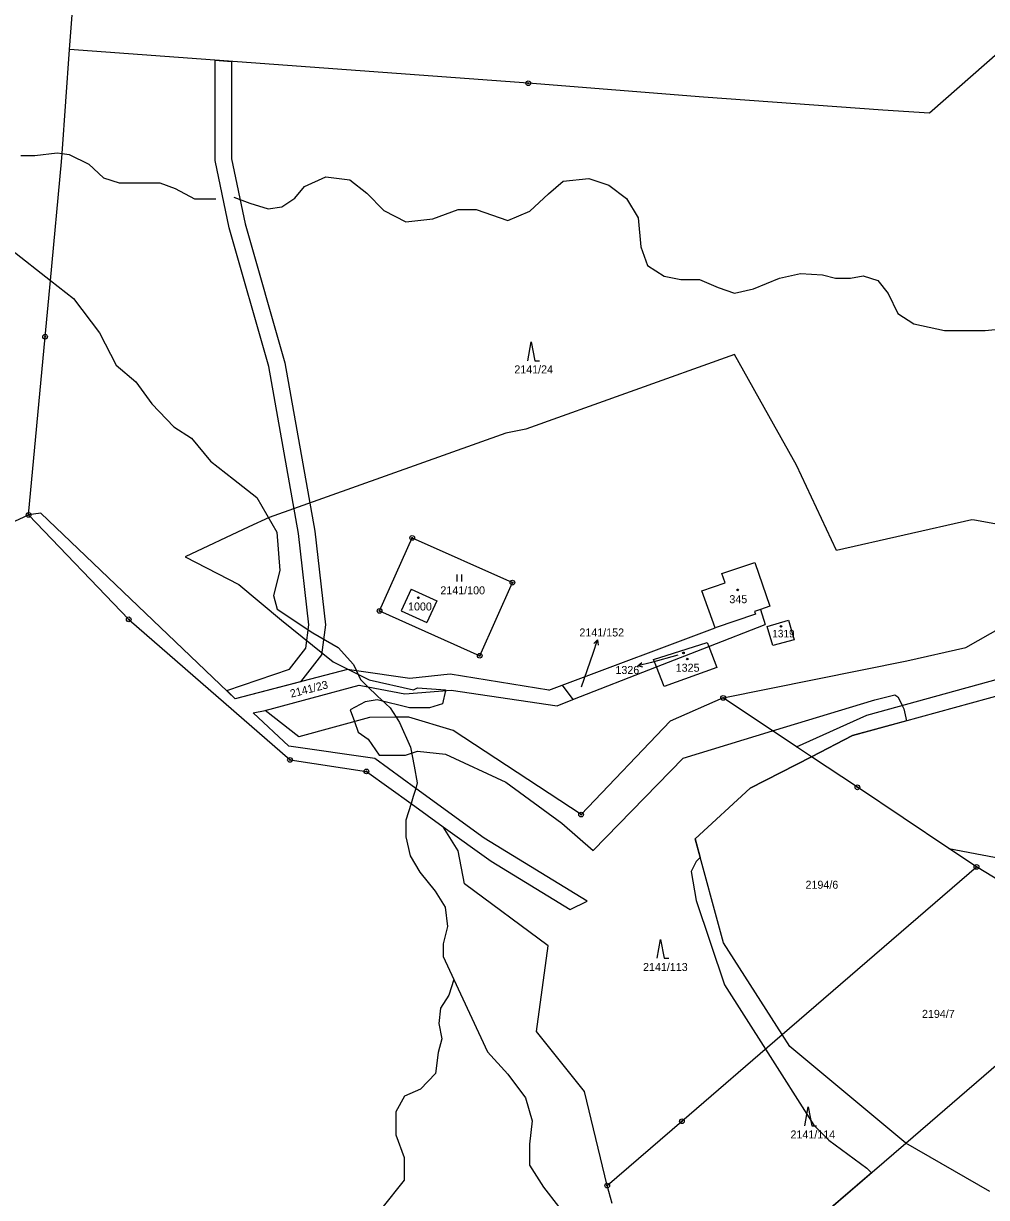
# Model space of a CAD drawing. Extents: x -439246 to -433691, y -1130252 to -1121148.
# Drawn here: x -435202 to -434997.5, y -1125650.6 to -1125401.2 of the extents above; entities that cross this region are included whole.
import ezdxf

# ---------------------------------------------------------------- set-up
doc = ezdxf.new("R2010")
doc.units = 0
for name, color, linetype in [('Vrstva 1', 7, 'Continuous'), ('Vrstva 16', 7, 'Continuous'), ('Vrstva 18', 7, 'Continuous'), ('Vrstva 19', 7, 'Continuous'), ('Vrstva 24', 7, 'Continuous'), ('Vrstva 25', 7, 'Continuous'), ('Vrstva 3', 7, 'Continuous'), ('Vrstva 30', 7, 'Continuous'), ('Vrstva 37', 7, 'Continuous'), ('Vrstva 4', 7, 'Continuous'), ('Vrstva 52', 7, 'Continuous')]:
    doc.layers.add(name, color=color, linetype=linetype)

msp = doc.modelspace()

# ---------------------------------------------------------------- linework, layer by layer
at = {"layer": 'Vrstva 1'}
for p, q in [((-435192.2, -1125406.77), (-435191.19, -1125392.8)), ((-435193.8, -1125428.86), (-435192.2, -1125406.77)), ((-435094.79, -1125413.92), (-435192.2, -1125406.77)), ((-435197.39, -1125467.76), (-435196.28, -1125455.81)), ((-435200.92, -1125505.62), (-435197.39, -1125467.76))]:
    msp.add_line(p, q, dxfattribs=at)
for points in [[(-434988.68, -1125401.95), (-435009.59, -1125420.25)], [(-435057.61, -1125416.9), (-435094.79, -1125413.92)], [(-435019.5, -1125419.63), (-435057.61, -1125416.9)], [(-435009.59, -1125420.25), (-435019.5, -1125419.63)], [(-435193.93, -1125430.63), (-435193.8, -1125428.86)], [(-435196.28, -1125455.81), (-435193.93, -1125430.63)], [(-435234.91, -1125521.29), (-435200.92, -1125505.62)], [(-435198.33, -1125505.22), (-435200.92, -1125505.62)], [(-435200.92, -1125505.62), (-435179.64, -1125527.79)], [(-435157.01, -1125544.65), (-435198.33, -1125505.22)], [(-435126.37, -1125526.01), (-435119.43, -1125510.49)], [(-435119.43, -1125510.49), (-435098.16, -1125520)], [(-435057.91, -1125521.71), (-435052.99, -1125520.03), (-435053.65, -1125518.08), (-435046.69, -1125515.7)], [(-435046.69, -1125515.7), (-435043.49, -1125524.97), (-435045.5, -1125525.68)], [(-435119.69, -1125521.36), (-435121.77, -1125525.97)], [(-435119.69, -1125521.36), (-435114.22, -1125523.83)], [(-435105.1, -1125535.52), (-435098.16, -1125520)], [(-435001.84, -1125533.79), (-434976.15, -1125519.18)], [(-435114.22, -1125523.83), (-435116.3, -1125528.43)], [(-435055.1, -1125529.6), (-435057.91, -1125521.71)], [(-435126.37, -1125526.01), (-435105.1, -1125535.52)], [(-435121.77, -1125525.97), (-435116.3, -1125528.43)], [(-435045.5, -1125525.68), (-435046.74, -1125526.12)], [(-435046.74, -1125526.12), (-435046.56, -1125526.71)], [(-435045.5, -1125525.68), (-435044.49, -1125528.87)], [(-435179.64, -1125527.79), (-435145.39, -1125557.65)], [(-435056.45, -1125533.55), (-435044.49, -1125528.87)], [(-435046.56, -1125526.71), (-435055.1, -1125529.6)], [(-435044.06, -1125529.34), (-435039.49, -1125527.98), (-435038.32, -1125532.12), (-435042.87, -1125533.32), (-435044.06, -1125529.34)], [(-435087.62, -1125541.8), (-435055.1, -1125529.6)], [(-435068.18, -1125536.32), (-435056.78, -1125532.69), (-435056.45, -1125533.55)], [(-435067.57, -1125537.9), (-435056.45, -1125533.55)], [(-435056.45, -1125533.55), (-435054.73, -1125538.01), (-435065.96, -1125542.06), (-435067.57, -1125537.9)], [(-435014.37, -1125536.57), (-435001.84, -1125533.79)], [(-435067.57, -1125537.9), (-435068.18, -1125536.32)], [(-435133.16, -1125538.45), (-435157.01, -1125544.65)], [(-435131.3, -1125538.72), (-435133.16, -1125538.45)], [(-435119.97, -1125540.36), (-435131.3, -1125538.72)], [(-435085.3, -1125544.84), (-435067.57, -1125537.9)], [(-435053.4, -1125544.49), (-435014.37, -1125536.57)], [(-435022.88, -1125548.13), (-434980.29, -1125536.37)], [(-435111.41, -1125539.45), (-435119.97, -1125540.36)], [(-435090.44, -1125542.86), (-435111.41, -1125539.45)], [(-435150.69, -1125547.12), (-435130.69, -1125541.75)], [(-435130.69, -1125541.75), (-435128.84, -1125542.11)], [(-435128.84, -1125542.11), (-435120.99, -1125543.62)], [(-435120.99, -1125543.62), (-435111.15, -1125542.81)], [(-435111.15, -1125542.81), (-435088.64, -1125546.15)], [(-435090.44, -1125542.86), (-435087.62, -1125541.8)], [(-435087.62, -1125541.8), (-435085.3, -1125544.84)], [(-435025.91, -1125552.49), (-434986.23, -1125541.55)], [(-435088.64, -1125546.15), (-435085.3, -1125544.84)], [(-435053.4, -1125544.49), (-435064.66, -1125549.42)], [(-435037.86, -1125554.84), (-435053.4, -1125544.49)], [(-435153.19, -1125547.67), (-435150.69, -1125547.12)], [(-435145.67, -1125554.75), (-435153.19, -1125547.67)], [(-435143.52, -1125552.73), (-435150.69, -1125547.12)], [(-435128.52, -1125548.63), (-435143.52, -1125552.73)], [(-435122.85, -1125548.59), (-435128.52, -1125548.63)], [(-435120.15, -1125548.57), (-435122.85, -1125548.59)], [(-435110.75, -1125551.4), (-435120.15, -1125548.57)], [(-435037.86, -1125554.84), (-435022.88, -1125548.13)], [(-435064.66, -1125549.42), (-435083.57, -1125569.26)], [(-435083.57, -1125569.26), (-435110.75, -1125551.4)], [(-435034.64, -1125556.98), (-435025.91, -1125552.49)], [(-435127.38, -1125557.37), (-435145.67, -1125554.75)], [(-435034.64, -1125556.98), (-435037.86, -1125554.84)], [(-435145.39, -1125557.65), (-435129.16, -1125560.08)], [(-435118.69, -1125563.7), (-435127.38, -1125557.37)], [(-435047.65, -1125563.68), (-435034.64, -1125556.98)], [(-435024.89, -1125563.47), (-435034.64, -1125556.98)], [(-435129.16, -1125560.08), (-435119.68, -1125566.92)], [(-435104.14, -1125574.29), (-435118.69, -1125563.7)], [(-435059.34, -1125574.38), (-435047.65, -1125563.68)], [(-435005.44, -1125576.46), (-435024.89, -1125563.47)], [(-435119.68, -1125566.92), (-435112.83, -1125571.87)], [(-435109.68, -1125576.97), (-435112.83, -1125571.87)], [(-435112.83, -1125571.87), (-435102.66, -1125579.13)], [(-435082.3, -1125587.67), (-435104.14, -1125574.29)], [(-435053.34, -1125596.52), (-435059.34, -1125574.38)], [(-435108.32, -1125583.95), (-435109.68, -1125576.97)], [(-435005.44, -1125576.46), (-434937.66, -1125589.35)], [(-434999.6, -1125580.36), (-435005.44, -1125576.46)], [(-435102.66, -1125579.13), (-435085.88, -1125589.41)], [(-435040.84, -1125616), (-434999.6, -1125580.36)], [(-434968.52, -1125599.25), (-434999.6, -1125580.36)], [(-435090.58, -1125597.13), (-435108.32, -1125583.95)], [(-435085.88, -1125589.41), (-435082.3, -1125587.67)], [(-435093.02, -1125615.36), (-435090.58, -1125597.13)], [(-435040.84, -1125616), (-435053.34, -1125596.52)], [(-435014.64, -1125639.05), (-434968.52, -1125599.25)], [(-435082.87, -1125628.06), (-435093.02, -1125615.36)], [(-435062.15, -1125634.4), (-435040.84, -1125616)], [(-435039.22, -1125618.53), (-435040.84, -1125616)], [(-435014.64, -1125639.05), (-435039.22, -1125618.53)], [(-435078.02, -1125648.06), (-435082.87, -1125628.06)], [(-435078.02, -1125648.06), (-435062.15, -1125634.4)], [(-435038.13, -1125659.3), (-435014.64, -1125639.05)], [(-434996.75, -1125649.32), (-435014.64, -1125639.05)], [(-435076.96, -1125651.87), (-435078.02, -1125648.06)]]:
    msp.add_lwpolyline(points, dxfattribs=at)
at = {"layer": 'Vrstva 16'}
for p, q in [((-435081.03, -1125534.99), (-435080.07, -1125532.15)), ((-435068.64, -1125536.93), (-435071.54, -1125537.7))]:
    msp.add_line(p, q, dxfattribs=at)
for points in [[(-435080.87, -1125532.94), (-435080.07, -1125532.15), (-435079.92, -1125533.25)], [(-435083.45, -1125542.16), (-435081.03, -1125534.99)], [(-435063.01, -1125535.43), (-435068.64, -1125536.93)], [(-435070.44, -1125537.93), (-435071.54, -1125537.7), (-435070.7, -1125536.96)]]:
    msp.add_lwpolyline(points, dxfattribs=at)
at = {"layer": 'Vrstva 24'}
for centre, radius in [((-435094.79, -1125413.92), 0.5), ((-435094.79, -1125413.92), 0.1), ((-435197.39, -1125467.76), 0.5), ((-435197.39, -1125467.76), 0.1), ((-435200.92, -1125505.62), 0.5), ((-435200.92, -1125505.62), 0.1), ((-435119.43, -1125510.49), 0.5), ((-435119.43, -1125510.49), 0.1), ((-435098.16, -1125520), 0.5), ((-435098.16, -1125520), 0.1), ((-435126.37, -1125526.01), 0.5), ((-435126.37, -1125526.01), 0.1), ((-435179.64, -1125527.79), 0.5), ((-435179.64, -1125527.79), 0.1), ((-435105.1, -1125535.52), 0.5), ((-435105.1, -1125535.52), 0.1), ((-435053.4, -1125544.49), 0.5), ((-435053.4, -1125544.49), 0.1), ((-435145.39, -1125557.65), 0.5), ((-435145.39, -1125557.65), 0.1), ((-435129.16, -1125560.08), 0.5), ((-435129.16, -1125560.08), 0.1), ((-435024.89, -1125563.47), 0.5), ((-435024.89, -1125563.47), 0.1), ((-435083.57, -1125569.26), 0.5), ((-435083.57, -1125569.26), 0.1), ((-434999.6, -1125580.36), 0.5), ((-434999.6, -1125580.36), 0.1), ((-435062.15, -1125634.4), 0.5), ((-435062.15, -1125634.4), 0.1), ((-435078.02, -1125648.06), 0.5), ((-435078.02, -1125648.06), 0.1)]:
    msp.add_circle(centre, radius, dxfattribs=at)
at = {"layer": 'Vrstva 25'}
for p, q in [((-435109.89, -1125519.78), (-435109.89, -1125518.28)), ((-435108.89, -1125519.78), (-435108.89, -1125518.28))]:
    msp.add_line(p, q, dxfattribs=at)
for points in [[(-435094.87, -1125472.85), (-435094.17, -1125468.85), (-435093.37, -1125472.85), (-435092.37, -1125472.85)], [(-435067.41, -1125599.79), (-435066.71, -1125595.79), (-435065.91, -1125599.79), (-435064.91, -1125599.79)], [(-435036.08, -1125635.35), (-435035.38, -1125631.35), (-435034.58, -1125635.35), (-435033.58, -1125635.35)]]:
    msp.add_lwpolyline(points, dxfattribs=at)
for centre in [(-435050.31, -1125521.53), (-435118.13, -1125523.21), (-435041.1, -1125529.29), (-435061.83, -1125534.91), (-435061.01, -1125536.22)]:
    msp.add_circle(centre, 0.175, dxfattribs=at)
at = {"layer": 'Vrstva 3'}
for points in [[(-435057.91, -1125521.71), (-435052.99, -1125520.03), (-435053.65, -1125518.08), (-435046.69, -1125515.7)], [(-435046.69, -1125515.7), (-435043.49, -1125524.97), (-435045.5, -1125525.68)], [(-435119.69, -1125521.36), (-435121.77, -1125525.97)], [(-435119.69, -1125521.36), (-435114.22, -1125523.83)], [(-435114.22, -1125523.83), (-435116.3, -1125528.43)], [(-435055.1, -1125529.6), (-435057.91, -1125521.71)], [(-435121.77, -1125525.97), (-435116.3, -1125528.43)], [(-435045.5, -1125525.68), (-435046.74, -1125526.12)], [(-435046.74, -1125526.12), (-435046.56, -1125526.71)], [(-435046.56, -1125526.71), (-435055.1, -1125529.6)], [(-435044.06, -1125529.34), (-435039.49, -1125527.98), (-435038.32, -1125532.12), (-435042.87, -1125533.32), (-435044.06, -1125529.34)], [(-435068.18, -1125536.32), (-435056.78, -1125532.69), (-435056.45, -1125533.55)], [(-435056.45, -1125533.55), (-435054.73, -1125538.01), (-435065.96, -1125542.06), (-435067.57, -1125537.9)], [(-435067.57, -1125537.9), (-435068.18, -1125536.32)]]:
    msp.add_lwpolyline(points, dxfattribs=at)
at = {"layer": 'Vrstva 30'}
msp.add_lwpolyline([(-435161.3, -1125409.04), (-435157.8, -1125409.3), (-435157.78, -1125429.96), (-435154.88, -1125443.79), (-435146.49, -1125473.3), (-435140.11, -1125509.06), (-435137.83, -1125528.98), (-435138.72, -1125535.34), (-435143.16, -1125541.05), (-435157.01, -1125544.65), (-435158.82, -1125542.92), (-435145.53, -1125538.39), (-435142.06, -1125533.93), (-435141.36, -1125528.93), (-435143.58, -1125509.56), (-435149.91, -1125474.08), (-435158.28, -1125444.63), (-435161.28, -1125430.32), (-435161.3, -1125409.04)], dxfattribs=at)
at = {"layer": 'Vrstva 37'}
for centre in [(-435050.31, -1125521.53), (-435118.13, -1125523.21), (-435041.1, -1125529.29), (-435061.01, -1125536.22)]:
    msp.add_circle(centre, 0.175, dxfattribs=at)
at = {"layer": 'Vrstva 4'}
for points in [[(-435199.56, -1125429.27), (-435194.81, -1125428.71)], [(-435194.81, -1125428.71), (-435193.8, -1125428.86)], [(-435193.8, -1125428.86), (-435192.31, -1125429.08)], [(-435192.31, -1125429.08), (-435188.1, -1125431.09)], [(-435202.56, -1125429.27), (-435199.56, -1125429.27)], [(-435188.1, -1125431.09), (-435184.99, -1125433.98)], [(-435184.99, -1125433.98), (-435181.68, -1125435.07)], [(-435142.28, -1125435.84), (-435137.77, -1125433.83)], [(-435137.77, -1125433.83), (-435132.67, -1125434.45)], [(-435181.68, -1125435.07), (-435176.78, -1125435.07)], [(-435176.78, -1125435.07), (-435173.04, -1125435.07)], [(-435173.04, -1125435.07), (-435169.77, -1125436.31)], [(-435169.77, -1125436.31), (-435165.7, -1125438.45)], [(-435144.39, -1125438.31), (-435142.28, -1125435.84)], [(-435132.67, -1125434.45), (-435129.08, -1125437.29)], [(-435090.52, -1125437.42), (-435087.35, -1125434.7)], [(-435087.35, -1125434.7), (-435081.93, -1125434.15)], [(-435081.93, -1125434.15), (-435077.68, -1125435.55)], [(-435077.68, -1125435.55), (-435073.92, -1125438.4)], [(-435165.7, -1125438.45), (-435161.16, -1125438.45)], [(-435157.35, -1125438.09), (-435153.9, -1125439.36)], [(-435147.11, -1125440.2), (-435144.39, -1125438.31)], [(-435129.08, -1125437.29), (-435125.44, -1125440.98)], [(-435094.48, -1125441.11), (-435090.52, -1125437.42)], [(-435073.92, -1125438.4), (-435071.44, -1125442.48)], [(-435153.9, -1125439.36), (-435150.05, -1125440.63)], [(-435150.05, -1125440.63), (-435147.11, -1125440.2)], [(-435125.44, -1125440.98), (-435120.82, -1125443.37)], [(-435115.06, -1125442.71), (-435109.65, -1125440.71)], [(-435109.65, -1125440.71), (-435105.83, -1125440.71)], [(-435105.83, -1125440.71), (-435099.13, -1125443.06)], [(-435099.13, -1125443.06), (-435094.48, -1125441.11)], [(-435120.82, -1125443.37), (-435115.06, -1125442.71)], [(-435071.44, -1125442.48), (-435070.85, -1125448.66)], [(-435070.85, -1125448.66), (-435069.49, -1125452.64)], [(-435204.55, -1125449.31), (-435196.28, -1125455.81)], [(-435069.49, -1125452.64), (-435065.91, -1125454.91)], [(-435196.28, -1125455.81), (-435191.36, -1125459.66)], [(-435065.91, -1125454.91), (-435062.39, -1125455.58)], [(-435062.39, -1125455.58), (-435058.45, -1125455.58)], [(-435058.45, -1125455.58), (-435054.45, -1125457.28)], [(-435046.96, -1125457.61), (-435041.44, -1125455.34)], [(-435041.44, -1125455.34), (-435036.98, -1125454.31)], [(-435036.98, -1125454.31), (-435032.31, -1125454.61)], [(-435032.31, -1125454.61), (-435029.55, -1125455.3)], [(-435029.55, -1125455.3), (-435026.37, -1125455.3)], [(-435026.37, -1125455.3), (-435023.67, -1125454.84)], [(-435023.67, -1125454.84), (-435020.52, -1125455.82)], [(-435020.52, -1125455.82), (-435018.37, -1125458.55)], [(-435054.45, -1125457.28), (-435051.02, -1125458.49)], [(-435051.02, -1125458.49), (-435046.96, -1125457.61)], [(-435018.37, -1125458.55), (-435016.34, -1125462.86)], [(-435191.36, -1125459.66), (-435185.83, -1125466.91)], [(-435016.34, -1125462.86), (-435012.88, -1125465.04)], [(-435012.88, -1125465.04), (-435006.37, -1125466.44)], [(-435006.37, -1125466.44), (-434997.77, -1125466.44)], [(-434997.77, -1125466.44), (-434983.78, -1125465.02)], [(-435185.83, -1125466.91), (-435182.29, -1125473.78)], [(-435182.29, -1125473.78), (-435178.11, -1125477.32)], [(-435178.11, -1125477.32), (-435174.73, -1125482.04)], [(-435174.73, -1125482.04), (-435170.07, -1125486.92)], [(-435170.07, -1125486.92), (-435166.31, -1125489.34)], [(-435166.31, -1125489.34), (-435162.27, -1125494.16)], [(-435162.27, -1125494.16), (-435157.4, -1125498.02)], [(-435157.4, -1125498.02), (-435152.43, -1125501.88)], [(-435152.43, -1125501.88), (-435148.21, -1125509.3)], [(-435148.21, -1125509.3), (-435147.55, -1125517.42)], [(-435147.55, -1125517.42), (-435148.87, -1125522.7)], [(-435148.87, -1125522.7), (-435148.11, -1125525.65)], [(-435148.11, -1125525.65), (-435140.56, -1125530.68)], [(-435140.56, -1125530.68), (-435135.14, -1125533.78)], [(-435135.14, -1125533.78), (-435131.93, -1125537.4)], [(-435131.93, -1125537.4), (-435131.3, -1125538.72)], [(-435131.3, -1125538.72), (-435130.4, -1125540.56)], [(-435130.4, -1125540.56), (-435128.84, -1125542.11)], [(-435128.84, -1125542.11), (-435126.88, -1125544.04)], [(-435126.88, -1125544.04), (-435124.1, -1125546.59)], [(-435124.1, -1125546.59), (-435122.85, -1125548.59)], [(-435122.85, -1125548.59), (-435122.15, -1125549.7)], [(-435122.15, -1125549.7), (-435119.78, -1125554.95)], [(-435119.78, -1125554.95), (-435118.99, -1125558.99)], [(-435118.99, -1125558.99), (-435118.36, -1125562.55)], [(-435118.69, -1125563.7), (-435119.2, -1125565.42)], [(-435118.36, -1125562.55), (-435118.69, -1125563.7)], [(-435119.2, -1125565.42), (-435119.68, -1125566.92)], [(-435119.68, -1125566.92), (-435120.81, -1125570.44)], [(-435120.81, -1125570.44), (-435120.81, -1125573.96)], [(-435120.81, -1125573.96), (-435119.85, -1125578)], [(-435119.85, -1125578), (-435117.84, -1125581.52)], [(-435117.84, -1125581.52), (-435114.56, -1125585.5)], [(-435114.56, -1125585.5), (-435112.47, -1125588.9)], [(-435112.47, -1125588.9), (-435111.92, -1125593.05)], [(-435111.92, -1125593.05), (-435112.85, -1125596.7)], [(-435112.85, -1125596.7), (-435112.85, -1125599.43)], [(-435112.85, -1125599.43), (-435110.61, -1125604.27)], [(-435110.61, -1125604.27), (-435111.64, -1125607.59)], [(-435110.61, -1125604.27), (-435103.44, -1125619.66)], [(-435111.64, -1125607.59), (-435113.46, -1125610.37)], [(-435113.46, -1125610.37), (-435113.76, -1125613.62)], [(-435113.76, -1125613.62), (-435113.12, -1125616.86)], [(-435113.12, -1125616.86), (-435113.91, -1125619.77)], [(-435113.91, -1125619.77), (-435114.46, -1125624.22)], [(-435103.44, -1125619.66), (-435099.13, -1125624.39)], [(-435114.46, -1125624.22), (-435117.71, -1125627.55)], [(-435099.13, -1125624.39), (-435095.39, -1125629.44)], [(-435117.71, -1125627.55), (-435121.06, -1125629.07)], [(-435121.06, -1125629.07), (-435122.93, -1125632.39)], [(-435095.39, -1125629.44), (-435093.98, -1125634.33)], [(-435122.93, -1125632.39), (-435122.93, -1125637.29)], [(-435093.98, -1125634.33), (-435094.56, -1125639.26)], [(-435122.93, -1125637.29), (-435121.18, -1125642.06)], [(-435094.56, -1125639.26), (-435094.56, -1125643.74)], [(-435121.18, -1125642.06), (-435121.18, -1125646.9)], [(-435094.56, -1125643.74), (-435091.59, -1125648.42)], [(-435121.18, -1125646.9), (-435125.92, -1125652.84)], [(-435091.59, -1125648.42), (-435088.4, -1125652.52)]]:
    msp.add_lwpolyline(points, dxfattribs=at)
at = {"layer": 'Vrstva 52'}
for points in [[(-434993.4, -1125507.95), (-435000, -1125506.72), (-435000.56, -1125506.62), (-435029.3, -1125513.15), (-435037.8, -1125495.05), (-435042.7, -1125486.32), (-435050.97, -1125471.57), (-435095.32, -1125487.38), (-435099.58, -1125488.23), (-435149.85, -1125506.13), (-435154.16, -1125508.15), (-435167.67, -1125514.49), (-435156.25, -1125520.4), (-435147.2, -1125527.96), (-435136.22, -1125536.81), (-435132.84, -1125538.5), (-435129.72, -1125540.06), (-435128.55, -1125540.64), (-435119.18, -1125542.77), (-435118.33, -1125542.34), (-435112.36, -1125542.77), (-435112.39, -1125542.91), (-435113, -1125545.75), (-435115.77, -1125546.6), (-435120.03, -1125546.6), (-435126.85, -1125544.9), (-435129.4, -1125545.33), (-435132.6, -1125547.03), (-435131.7, -1125549.5), (-435130.89, -1125551.72), (-435128.76, -1125553.21), (-435126.42, -1125556.62), (-435120.88, -1125556.62), (-435119.81, -1125556.26), (-435118.33, -1125555.76), (-435112.36, -1125556.4), (-435099.58, -1125562.37), (-435087.65, -1125571.1), (-435081.04, -1125576.86), (-435061.87, -1125557.26), (-435042.89, -1125551.49), (-435021.18, -1125544.9), (-435016.92, -1125543.84), (-435016.28, -1125544.26), (-435015.75, -1125545.34), (-435015.39, -1125546.06), (-435015.01, -1125546.82), (-435014.48, -1125549.34), (-435025.91, -1125552.49), (-435034.64, -1125556.98), (-435047.65, -1125563.68), (-435059.34, -1125574.38), (-435058.25, -1125578.4), (-435059.1, -1125579.2), (-435060.17, -1125581.33), (-435059.1, -1125587.51), (-435053.14, -1125605.4), (-435044.43, -1125619.1), (-435034.18, -1125635.22), (-435030.98, -1125638.42), (-435022.89, -1125644.38), (-435021.93, -1125645.34)], [(-435021.93, -1125645.34), (-435038.13, -1125659.3), (-435047.31, -1125667.29), (-435047.94, -1125667.84), (-435044.69, -1125672.4), (-435027.36, -1125673.85), (-435024.88, -1125690.52), (-435016.08, -1125704.39), (-435013.98, -1125742.52), (-435000, -1125744.16), (-434962.79, -1125748.54)]]:
    msp.add_lwpolyline(points, dxfattribs=at)

# ---------------------------------------------------------------- texts
at = {"layer": 'Vrstva 16'}
for s, p in [('2141/152', (-435083.93, -1125531.43)), ('1326', (-435076.28, -1125539.4))]:
    msp.add_text(s, height=1.7, dxfattribs=at).set_placement(p)
at = {"layer": 'Vrstva 18'}
for s, height, p in [('2141/24', 1.7, (-435097.75, -1125475.55)), ('2141/100', 1.7, (-435113.46, -1125522.48)), ('2141/152', 0.1, (-435083.71, -1125542.16)), ('2194/6', 1.7, (-435035.91, -1125585.01)), ('2141/113', 1.7, (-435070.42, -1125602.49)), ('2194/7', 1.7, (-435011.18, -1125612.44)), ('2141/114', 1.7, (-435039.1, -1125638.05))]:
    msp.add_text(s, height=height, dxfattribs=at).set_placement(p)
msp.add_text('2141/23', height=1.7, rotation=14.4004, dxfattribs=at).set_placement((-435145.14, -1125544.44))
at = {"layer": 'Vrstva 19'}
for s, height, p in [('345', 1.7, (-435052.08, -1125524.36)), ('1000', 1.7, (-435120.32, -1125525.91)), ('1319', 1.6, (-435042.98, -1125531.62)), ('1326', 0.1, (-435063.14, -1125535.43)), ('1325', 1.7, (-435063.48, -1125538.92))]:
    msp.add_text(s, height=height, dxfattribs=at).set_placement(p)

doc.saveas('drawing.dxf')
